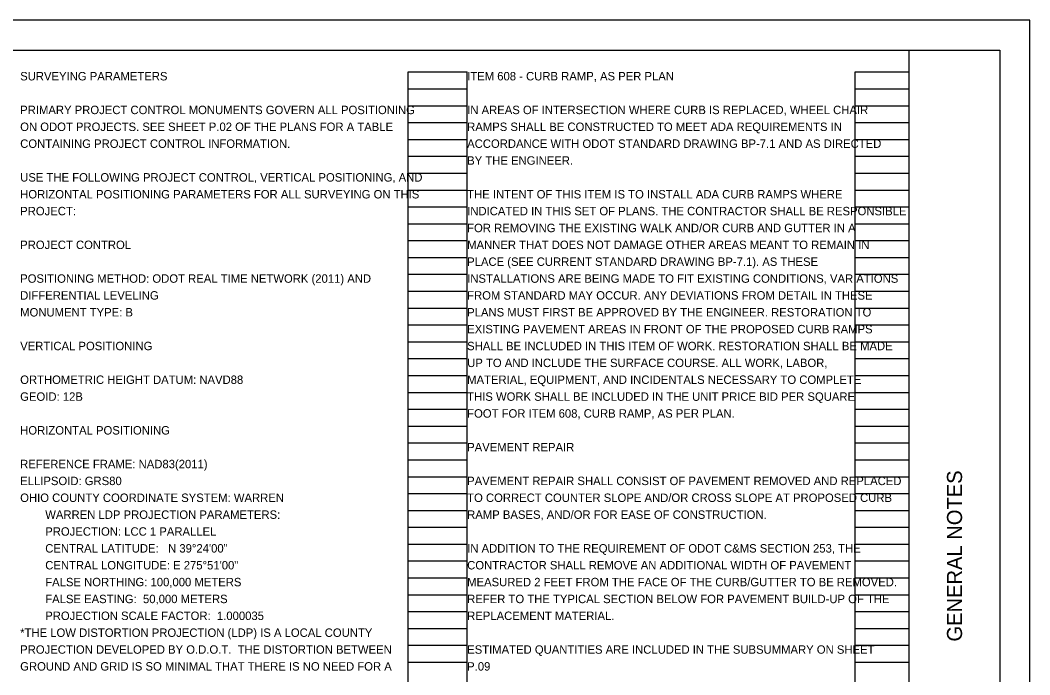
# Model space of a CAD drawing. Extents: x 0 to 34, y 0 to 22.
# Drawn here: x 17.24 to 34, y 11.13 to 22 of the extents above; entities that cross this region are included whole.
import ezdxf

# ---------------------------------------------------------------- set-up
doc = ezdxf.new("R2010")
doc.units = 0
for name, color, linetype in [('SH_Border', 7, 'Continuous'), ('SH_Cut_Line', 7, 'Continuous'), ('SH_Data', 7, 'Continuous'), ('SH_Text', 7, 'Continuous')]:
    doc.layers.add(name, color=color, linetype=linetype)

msp = doc.modelspace()

# ---------------------------------------------------------------- linework, layer by layer
at = {"layer": 'SH_Border'}
msp.add_line((32, 0.5), (32, 21.5), dxfattribs=at)
msp.add_lwpolyline([(1.5, 21.5), (33.5, 21.5), (33.5, 0.5), (1.5, 0.5)], close=True, dxfattribs=at)
at = {"layer": 'SH_Cut_Line'}
msp.add_lwpolyline([(0, 0), (34, 0), (34, 22), (0, 22)], close=True, dxfattribs=at)
at = {"layer": 'SH_Data'}
for p, q in [((23.68, 0.98), (23.68, 21.14)), ((23.68, 21.14), (24.66, 21.14)), ((24.66, 0.98), (24.66, 21.14)), ((31.1, 0.98), (31.1, 21.14)), ((31.1, 21.14), (32, 21.14)), ((32, 0.98), (32, 21.14)), ((23.68, 20.86), (24.66, 20.86)), ((31.1, 20.86), (32, 20.86)), ((23.68, 20.58), (24.66, 20.58)), ((31.1, 20.58), (32, 20.58)), ((23.68, 20.3), (24.66, 20.3)), ((31.1, 20.3), (32, 20.3)), ((23.68, 20.02), (24.66, 20.02)), ((31.1, 20.02), (32, 20.02)), ((23.68, 19.74), (24.66, 19.74)), ((31.1, 19.74), (32, 19.74)), ((23.68, 19.46), (24.66, 19.46)), ((31.1, 19.46), (32, 19.46)), ((23.68, 19.18), (24.66, 19.18)), ((31.1, 19.18), (32, 19.18)), ((23.68, 18.9), (24.66, 18.9)), ((31.1, 18.9), (32, 18.9)), ((23.68, 18.62), (24.66, 18.62)), ((31.1, 18.62), (32, 18.62)), ((23.68, 18.34), (24.66, 18.34)), ((31.1, 18.34), (32, 18.34)), ((23.68, 18.06), (24.66, 18.06)), ((31.1, 18.06), (32, 18.06)), ((23.68, 17.78), (24.66, 17.78)), ((31.1, 17.78), (32, 17.78)), ((23.68, 17.5), (24.66, 17.5)), ((31.1, 17.5), (32, 17.5)), ((23.68, 17.22), (24.66, 17.22)), ((31.1, 17.22), (32, 17.22)), ((23.68, 16.94), (24.66, 16.94)), ((31.1, 16.94), (32, 16.94)), ((23.68, 16.66), (24.66, 16.66)), ((31.1, 16.66), (32, 16.66)), ((23.68, 16.38), (24.66, 16.38)), ((31.1, 16.38), (32, 16.38)), ((23.68, 16.1), (24.66, 16.1)), ((31.1, 16.1), (32, 16.1)), ((23.68, 15.82), (24.66, 15.82)), ((31.1, 15.82), (32, 15.82)), ((23.68, 15.54), (24.66, 15.54)), ((31.1, 15.54), (32, 15.54)), ((23.68, 15.26), (24.66, 15.26)), ((31.1, 15.26), (32, 15.26)), ((23.68, 14.98), (24.66, 14.98)), ((31.1, 14.98), (32, 14.98)), ((23.68, 14.7), (24.66, 14.7)), ((31.1, 14.7), (32, 14.7)), ((23.68, 14.42), (24.66, 14.42)), ((31.1, 14.42), (32, 14.42)), ((23.68, 14.14), (24.66, 14.14)), ((31.1, 14.14), (32, 14.14)), ((23.68, 13.86), (24.66, 13.86)), ((31.1, 13.86), (32, 13.86)), ((23.68, 13.58), (24.66, 13.58)), ((31.1, 13.58), (32, 13.58)), ((23.68, 13.3), (24.66, 13.3)), ((31.1, 13.3), (32, 13.3)), ((23.68, 13.02), (24.66, 13.02)), ((31.1, 13.02), (32, 13.02)), ((23.68, 12.74), (24.66, 12.74)), ((31.1, 12.74), (32, 12.74)), ((23.68, 12.46), (24.66, 12.46)), ((31.1, 12.46), (32, 12.46)), ((23.68, 12.18), (24.66, 12.18)), ((31.1, 12.18), (32, 12.18)), ((23.68, 11.9), (24.66, 11.9)), ((31.1, 11.9), (32, 11.9)), ((23.68, 11.62), (24.66, 11.62)), ((31.1, 11.62), (32, 11.62)), ((23.68, 11.34), (24.66, 11.34)), ((31.1, 11.34), (32, 11.34))]:
    msp.add_line(p, q, dxfattribs=at)

# ---------------------------------------------------------------- texts
msp.add_text('GENERAL NOTES', height=0.25, rotation=90, dxfattribs=at).set_placement((32.875, 11.682))
at = {"layer": 'SH_Text'}
for s, p in [('SURVEYING PARAMETERS', (17.24, 21)), ('ITEM 608 - CURB RAMP, AS PER PLAN', (24.66, 21)), ('PRIMARY PROJECT CONTROL MONUMENTS GOVERN ALL POSITIONING ', (17.24, 20.44)), ('IN AREAS OF INTERSECTION WHERE CURB IS REPLACED, WHEEL CHAIR ', (24.66, 20.44)), ('ON ODOT PROJECTS. SEE SHEET P.02 OF THE PLANS FOR A TABLE ', (17.24, 20.16)), ('RAMPS SHALL BE CONSTRUCTED TO MEET ADA REQUIREMENTS IN ', (24.66, 20.16)), ('CONTAINING PROJECT CONTROL INFORMATION.', (17.24, 19.88)), ('ACCORDANCE WITH ODOT STANDARD DRAWING BP-7.1 AND AS DIRECTED ', (24.66, 19.88)), ('BY THE ENGINEER.', (24.66, 19.6)), ('USE THE FOLLOWING PROJECT CONTROL, VERTICAL POSITIONING, AND ', (17.24, 19.32)), ('HORIZONTAL POSITIONING PARAMETERS FOR ALL SURVEYING ON THIS ', (17.24, 19.04)), ('THE INTENT OF THIS ITEM IS TO INSTALL ADA CURB RAMPS WHERE', (24.66, 19.04)), ('PROJECT:', (17.24, 18.76)), ('INDICATED IN THIS SET OF PLANS. THE CONTRACTOR SHALL BE RESPONSIBLE', (24.66, 18.76)), ('FOR REMOVING THE EXISTING WALK AND/OR CURB AND GUTTER IN A', (24.66, 18.48)), ('PROJECT CONTROL', (17.24, 18.2)), ('MANNER THAT DOES NOT DAMAGE OTHER AREAS MEANT TO REMAIN IN', (24.66, 18.2)), ('PLACE (SEE CURRENT STANDARD DRAWING BP-7.1). AS THESE', (24.66, 17.92)), ('POSITIONING METHOD: ODOT REAL TIME NETWORK (2011) AND ', (17.24, 17.64)), ('INSTALLATIONS ARE BEING MADE TO FIT EXISTING CONDITIONS, VARIATIONS', (24.66, 17.64)), ('DIFFERENTIAL LEVELING', (17.24, 17.36)), ('FROM STANDARD MAY OCCUR. ANY DEVIATIONS FROM DETAIL IN THESE', (24.66, 17.36)), ('MONUMENT TYPE: B', (17.24, 17.08)), ('PLANS MUST FIRST BE APPROVED BY THE ENGINEER. RESTORATION TO ', (24.66, 17.08)), ('EXISTING PAVEMENT AREAS IN FRONT OF THE PROPOSED CURB RAMPS ', (24.66, 16.8)), ('VERTICAL POSITIONING', (17.24, 16.52)), ('SHALL BE INCLUDED IN THIS ITEM OF WORK. RESTORATION SHALL BE MADE ', (24.66, 16.52)), ('UP TO AND INCLUDE THE SURFACE COURSE. ALL WORK, LABOR,', (24.66, 16.24)), ('ORTHOMETRIC HEIGHT DATUM: NAVD88', (17.24, 15.96)), ('MATERIAL, EQUIPMENT, AND INCIDENTALS NECESSARY TO COMPLETE', (24.66, 15.96)), ('GEOID: 12B', (17.24, 15.68)), ('THIS WORK SHALL BE INCLUDED IN THE UNIT PRICE BID PER SQUARE', (24.66, 15.68)), ('FOOT FOR ITEM 608, CURB RAMP, AS PER PLAN.', (24.66, 15.4)), ('HORIZONTAL POSITIONING', (17.24, 15.12)), ('PAVEMENT REPAIR', (24.66, 14.84)), ('REFERENCE FRAME: NAD83(2011)', (17.24, 14.56)), ('ELLIPSOID: GRS80', (17.24, 14.28)), ('PAVEMENT REPAIR SHALL CONSIST OF PAVEMENT REMOVED AND REPLACED ', (24.66, 14.28)), ('OHIO COUNTY COORDINATE SYSTEM: WARREN', (17.24, 14)), ('TO CORRECT COUNTER SLOPE AND/OR CROSS SLOPE AT PROPOSED CURB ', (24.66, 14)), ('        WARREN LDP PROJECTION PARAMETERS:', (17.24, 13.72)), ('RAMP BASES, AND/OR FOR EASE OF CONSTRUCTION. ', (24.66, 13.72)), ('        PROJECTION: LCC 1 PARALLEL', (17.24, 13.44)), ('        CENTRAL LATITUDE:   N 39°24\'00"', (17.24, 13.16)), ('IN ADDITION TO THE REQUIREMENT OF ODOT C&MS SECTION 253, THE ', (24.66, 13.16)), ('        CENTRAL LONGITUDE: E 275°51\'00"', (17.24, 12.88)), ('CONTRACTOR SHALL REMOVE AN ADDITIONAL WIDTH OF PAVEMENT ', (24.66, 12.88)), ('        FALSE NORTHING: 100,000 METERS', (17.24, 12.6)), ('MEASURED 2 FEET FROM THE FACE OF THE CURB/GUTTER TO BE REMOVED. ', (24.66, 12.6)), ('        FALSE EASTING:  50,000 METERS', (17.24, 12.32)), ('REFER TO THE TYPICAL SECTION BELOW FOR PAVEMENT BUILD-UP OF THE ', (24.66, 12.32)), ('        PROJECTION SCALE FACTOR:  1.000035', (17.24, 12.04)), ('REPLACEMENT MATERIAL.', (24.66, 12.04)), ('*THE LOW DISTORTION PROJECTION (LDP) IS A LOCAL COUNTY ', (17.24, 11.76)), ('PROJECTION DEVELOPED BY O.D.O.T.  THE DISTORTION BETWEEN ', (17.24, 11.48)), ('ESTIMATED QUANTITIES ARE INCLUDED IN THE SUBSUMMARY ON SHEET ', (24.66, 11.48)), ('GROUND AND GRID IS SO MINIMAL THAT THERE IS NO NEED FOR A ', (17.24, 11.2)), ('P.09', (24.66, 11.2))]:
    msp.add_text(s, height=0.14, dxfattribs=at).set_placement(p)

doc.saveas('drawing.dxf')
